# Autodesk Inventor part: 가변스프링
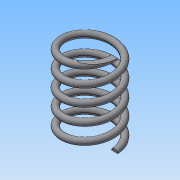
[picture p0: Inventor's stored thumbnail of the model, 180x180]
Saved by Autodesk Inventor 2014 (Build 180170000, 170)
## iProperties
Created: 2018-08
Part Number: 가변스프링
Material: 일반
Document SubType Name: Modeling
Designer: net
Density: 1 g/cm^3
Appearance: 기본값
Mass: 12.143 g
Surface Area: 98.6603 cm^2
Volume: 12.143 cm^3
Author: net
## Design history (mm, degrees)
sketch "스케치1"
  geometry: L1 (0, 0)-(-20, 0); L2 (-20, 0)-(-20, 67.25); L3 (-20, 67.25)-(0, 67.25); L4 (0, 67.25)-(0, 0); C1 r 2.5 at (-20, 0)
  constraints: 8 end point, 2 parallel, 1 centre point, 1 coincident, 1 horizontal, 1 perpendicular
  dimensions: "d0" = 5 diameter of C1; "d3" = 40 diameter of L2 L4; "d4" = 67.25 distance between parallel lines of L3 L1 (derived)
feature "코일1" sketch "스케치1" pitch "d5" = 10; turns "d7" = 5; dims "d6" = 67.25 (= d4), "d8" = 0, angle "d9" = 90 deg, angle "d10" = 90 deg, "d11" = 0, "d12" = 0
node "작업 평면1"
sketch "스케치2"
  geometry: L1 (17.5, 0)-(22.5, 0) reference; 1 further point
  constraints: 1 horizontal alignment
extrude "돌출1" cut sketch "스케치2" distance "d13" = 10; taper "d14" = 0 deg
sketch "스케치3"
  geometry: L1 (22.5, 0)-(17.5, 0) reference; L2 (22.5, 0)-(17.5, 0) reference; 1 further point
  constraints: 2 horizontal alignment
extrude "돌출2" cut sketch "스케치3" distance "d15" = 10; taper "d16" = 0 deg
node "솔리드1"
node "절단 모서리 투영1"
node "절단 모서리 투영2"
node "절단 모서리 투영3"
